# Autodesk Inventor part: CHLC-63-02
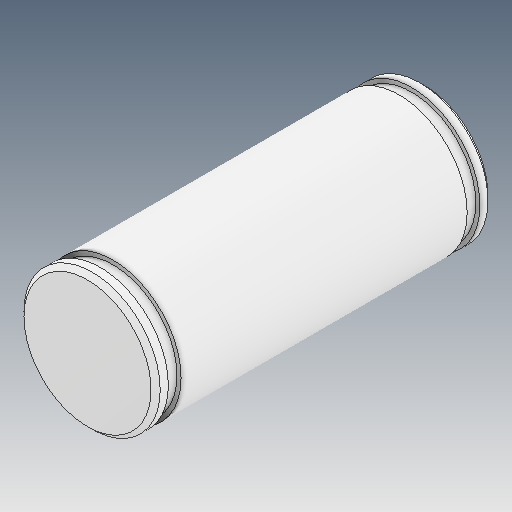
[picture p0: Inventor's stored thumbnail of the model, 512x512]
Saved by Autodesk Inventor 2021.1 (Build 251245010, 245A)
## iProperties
Created: 2021-05
Part Number: CHLC-63-02
Material: Ogólny
Document SubType Name: Modeling
Designer: user
Density: 1 g/cm^3
Appearance: Domyślna
Author: user
Revision Number: ÈÎºÎ
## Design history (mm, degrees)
feature "ÊäÈë1"
node "Bryła1"
